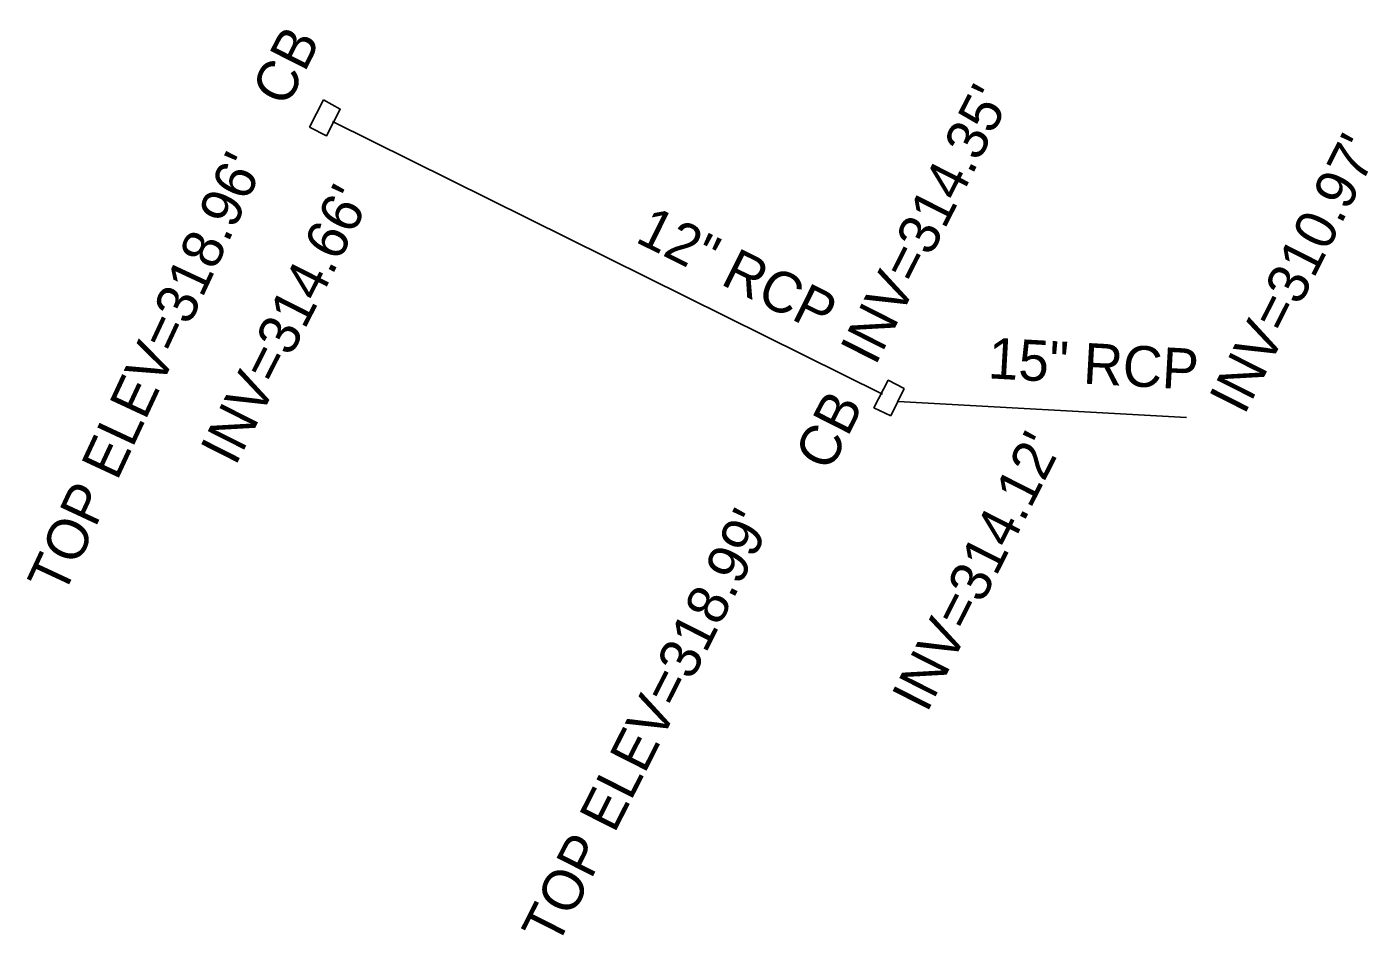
# Model space of a CAD drawing. Extents: x 1975859 to 1978323, y 778892 to 782836.
# Drawn here: x 1977868.4 to 1977999.9, y 782183 to 782272.1 of the extents above; entities that cross this region are included whole.
import ezdxf

# ---------------------------------------------------------------- set-up
doc = ezdxf.new("R2010")
doc.units = 0
for name, color, linetype in [('Exist Structure Minor Catch Basin', 7, 'Continuous'), ('Exist Structure Minor Catch Basin Text', 7, 'Continuous'), ('Exist Structure Minor Catch Basin Top Elevation', 7, 'Continuous'), ('Exist Structure Minor Pipes RCP 12 Inch', 7, 'Continuous'), ('Exist Structure Minor Pipes RCP 12 Inch Invert', 7, 'Continuous'), ('Exist Structure Minor Pipes RCP 12 Inch Text', 7, 'Continuous'), ('Exist Structure Minor Pipes RCP 15 Inch', 7, 'Continuous'), ('Exist Structure Minor Pipes RCP 15 Inch Invert', 7, 'Continuous'), ('Exist Structure Minor Pipes RCP 15 Inch Text', 7, 'Continuous')]:
    doc.layers.add(name, color=color, linetype=linetype)

msp = doc.modelspace()

# ---------------------------------------------------------------- linework, layer by layer
at = {"layer": 'Exist Structure Minor Catch Basin'}
for p, q in [((1977896.09, 782262.24), (1977897.45, 782264.92)), ((1977954.38, 782236.62), (1977953.06, 782233.96))]:
    msp.add_line(p, q, dxfattribs=at)
for points in [[(1977896.09, 782262.24), (1977897.74, 782261.39), (1977899.09, 782264.02), (1977897.45, 782264.92)], [(1977954.38, 782236.62), (1977952.81, 782237.45), (1977951.41, 782234.75), (1977953.06, 782233.96)]]:
    msp.add_lwpolyline(points, dxfattribs=at)
at = {"layer": 'Exist Structure Minor Pipes RCP 12 Inch'}
msp.add_line((1977898.34, 782262.82), (1977952.26, 782236.07), dxfattribs=at)
at = {"layer": 'Exist Structure Minor Pipes RCP 15 Inch'}
msp.add_line((1977953.8, 782235.37), (1977982.05, 782233.8), dxfattribs=at)

# ---------------------------------------------------------------- texts
at = {"layer": 'Exist Structure Minor Catch Basin Text'}
for p in [(1977893.85, 782264.1), (1977947.08, 782228.36)]:
    msp.add_text('CB', height=4, rotation=63.1198, dxfattribs=at).set_placement(p)
at = {"layer": 'Exist Structure Minor Catch Basin Top Elevation'}
for s, rotation, p in [("TOP ELEV=318.96'", 65.0303, (1977871.95, 782216.18)), ("TOP ELEV=318.99'", 63.1198, (1977920.32, 782181.8))]:
    msp.add_text(s, height=4, rotation=rotation, dxfattribs=at).set_placement(p)
at = {"layer": 'Exist Structure Minor Pipes RCP 12 Inch Invert'}
for s, p in [("INV=314.35'", (1977951.54, 782238.76)), ("INV=314.66'", (1977888.81, 782228.93))]:
    msp.add_text(s, height=4, rotation=63.1198, dxfattribs=at).set_placement(p)
at = {"layer": 'Exist Structure Minor Pipes RCP 12 Inch Text'}
msp.add_text('12" RCP', height=4, rotation=333.6136, dxfattribs=at).set_placement((1977927.9, 782251.06))
at = {"layer": 'Exist Structure Minor Pipes RCP 15 Inch Invert'}
for s, p in [("INV=310.97'", (1977987.71, 782233.93)), ("INV=314.12'", (1977956.59, 782204.73))]:
    msp.add_text(s, height=4, rotation=63.1198, dxfattribs=at).set_placement(p)
at = {"layer": 'Exist Structure Minor Pipes RCP 15 Inch Text'}
msp.add_text('15" RCP', height=4, rotation=356.8162, dxfattribs=at).set_placement((1977962.53, 782237.64))

doc.saveas('drawing.dxf')
